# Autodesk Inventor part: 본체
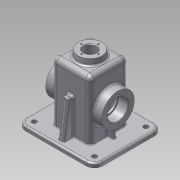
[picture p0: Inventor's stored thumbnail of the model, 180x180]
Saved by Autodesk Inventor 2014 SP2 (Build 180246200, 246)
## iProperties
Created: 2016-08
Part Number: 본체
Material: 알루미늄 6061
Document SubType Name: Modeling
Designer: user
Density: 2.71 g/cm^3
Appearance: 알루미늄 - 평지
Mass: 800.229 g
Surface Area: 911.927 cm^2
Volume: 295.287 cm^3
Author: user
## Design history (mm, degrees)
sketch "스케치1"
  geometry: L1 (-51, -57.5)-(51, -57.5); L2 (65, -43.5)-(65, 43.5); L3 (51, 57.5)-(-51, 57.5); L4 (-65, 43.5)-(-65, -43.5); L5 (-65, -57.5)-(65, 57.5); L6 (65, -57.5)-(-65, 57.5); A1 r 14 centre (-51, 43.5) between (-51, 57.5) and (-65, 43.5); A2 r 14 centre (-51, -43.5) between (-65, -43.5) and (-51, -57.5); A3 r 14 centre (51, -43.5) between (51, -57.5) and (65, -43.5); A4 r 14 centre (51, 43.5) between (65, 43.5) and (51, 57.5); 1 further point
  constraints: 12 end point, 8 point on circle, 8 point on line, 8 tangent, 4 centre point, 3 equal radius, 2 midpoint, 2 parallel, 1 horizontal, 1 perpendicular
  dimensions: "d0" = 130 distance of L6.end L5.end; "d1" = 115 distance of L5.end L6.start; "d4" = 14 radius of A1
extrude "돌출1" new body sketch "스케치1" distance "d2" = 10; taper "d3" = 0 deg
sketch "스케치2"
  geometry: L1 (-51, 0)-(51, 0) reference; L2 (32.5, 0)-(-32.5, 0); L3 (-32.5, 0)-(-32.5, 110); L4 (-32.5, 110)-(32.5, 110); L5 (32.5, 110)-(32.5, 0); 3 further points
  constraints: 8 end point, 2 midpoint, 2 parallel, 1 coincident, 1 horizontal, 1 perpendicular, 1 point on line
  dimensions: "d5" = 65 distance of L3.end L4.end; "d6" = 110 distance of L4.end L2.start
extrude "돌출2" join sketch "스케치2" stored distance "d7" = 65; taper "d8" = 0 deg
sketch "스케치3"
  geometry: L1 (27.5, 27.5)-(-27.5, 27.5); L2 (-27.5, 27.5)-(-27.5, -27.5); L3 (-27.5, -27.5)-(27.5, -27.5); L4 (27.5, -27.5)-(27.5, 27.5); L5 (27.5, 27.5)-(-27.5, -27.5); L6 (-27.5, 27.5)-(27.5, -27.5); 1 further point
  constraints: 12 end point, 2 midpoint, 2 parallel, 1 horizontal, 1 perpendicular
  dimensions: "d9" = 55 distance of L3.end L2.end; "d10" = 55 distance of L2.end L1.end
extrude "돌출3" cut sketch "스케치3" distance "d11" = 105; taper "d12" = 0 deg
sketch "스케치4"
  geometry: L1 (47.5, 55)-(-47.5, 55); L2 (47.5, 55)-(47.5, 82.5); L3 (-47.5, 82.5)-(-47.5, 55); L4 (32.5, 10)-(32.5, 110) reference; L5 (-32.5, 110)-(-32.5, 10) reference; L6 (47.5, 82.5)-(32.5, 82.5); L7 (-32.5, 82.5)-(-47.5, 82.5); L8 (32.5, 82.5)-(32.5, 55); L9 (-32.5, 82.5)-(-32.5, 55); 2 further points
  constraints: 14 end point, 6 point on line, 3 perpendicular, 1 horizontal, 1 midpoint, 1 parallel, 1 vertical alignment
  dimensions: "d13" = 55 distance from line of point (0, 0) L1; "d14" = 95 distance of L1.start L1.end; "d15" = 55 diameter of L6 L1; "d16" = 55 diameter of L7 L1
revolve "회전1" sketch "스케치4" stored, may be unused: angle "d17" = 90 deg
sketch "스케치5"
  geometry: L1 (47.5, 27.5)-(47.5, 82.5) reference; L2 (-47.5, 27.5)-(-47.5, 82.5) reference; L3 (47.5, 55)-(-47.5, 55); L4 (47.5, 55)-(47.5, 72.5); L5 (30.5, 72.2)-(30.5, 70); L6 (30.5, 70)-(27.5, 70); L7 (47.5, 72.5)-(30.8, 72.5); L8 (27.5, 0)-(27.5, 105) reference; L9 (-27.5, 0)-(-27.5, 105) reference; L10 (27.5, 55)-(27.5, 70); L11 (-47.5, 55)-(-47.5, 72.5); L12 (-47.5, 72.5)-(-30.8, 72.5); L13 (-30.5, 72.2)-(-30.5, 70); L14 (-30.5, 70)-(-27.5, 70); L15 (-27.5, 70)-(-27.5, 55); A1 r 0.3 centre (30.8, 72.2) between (30.8, 72.5) and (30.5, 72.2); A2 r 0.3 centre (-30.8, 72.2) between (-30.5, 72.2) and (-30.8, 72.5); 3 further points
  constraints: 22 end point, 12 point on line, 4 perpendicular, 4 point on circle, 4 tangent, 2 centre point, 2 midpoint, 2 parallel, 1 equal radius
  dimensions: "d18" = 17 distance between parallel lines of L5 L1; "d19" = 17 distance between parallel lines of L2 L13; "d20" = 35 diameter of L7 L3; "d21" = 30 diameter of L6 L3; "d22" = 35 diameter of L12 L3; "d23" = 30 diameter of L14 L3; "d146" = 0.3 radius of A1
revolve "회전2" sketch "스케치5" stored, may be unused: angle "d24" = 90 deg
node "작업 평면1"
sketch "스케치6"
  geometry: C1 r 20 at (0, 0); 1 further point
  constraints: 1 centre point, 1 coincident
  dimensions: "d26" = 40 diameter of C1
extrude "돌출4" join sketch "스케치6" stored distance "d27" = 105; taper "d28" = 7 deg
sketch "스케치7"
  geometry: L1 (-49.5, 10)-(-41.068, 70); L2 (-43.5, 10)-(-57.5, 10) reference; L3 (-57.5, 0)-(-57.5, 10) reference; L4 (-32.5, 110)-(-32.5, 10) reference; L5 (-41.068, 70)-(-32.5, 70); 1 further point
  constraints: 4 end point, 2 point on line, 1 perpendicular
  dimensions: "d29" = 8 distance of L1.start L2.end; "d30" = 8 deg angle of L1 L3; "d31" = 70 vertical distance of point (0, 0) L1.end
feature "리브1" sketch "스케치7" dims "d32" = 1, "d33" = 10, "d34" = 0, "d35" = 0, "d36" = 1, "d37" = 1
sketch "스케치8"
  geometry: L1 (57.5, 10)-(43.5, 10) reference; L2 (57.5, 0)-(57.5, 10) reference; L3 (32.5, 10)-(32.5, 110) reference; L4 (49.5, 10)-(41.068, 70); L5 (41.068, 70)-(32.5, 70); 1 further point
  constraints: 4 end point, 2 point on line, 1 perpendicular
  dimensions: "d38" = 70 vertical distance of point (0, 0) L4.end; "d39" = 8 deg angle of L4 L2; "d40" = 8 distance from line of L2 L4.start
feature "리브2" sketch "스케치8" dims "d41" = 1, "d42" = 10, "d43" = 0, "d44" = 0, "d45" = 1, "d46" = 1
sketch "스케치9"
  geometry: L1 (51, 10)-(-51, 10) reference; L2 (-47.5, 27.5)-(-32.5, 27.5) reference; L3 (-42.5, 10)-(-42.5, 27.5); L4 (-27.5, 0)-(-27.5, 105) reference; 1 further point
  constraints: 2 end point, 2 point on line, 1 perpendicular
  dimensions: "d47" = 15 distance between parallel lines of L4 L3
feature "리브3" sketch "스케치9" dims "d48" = 1, "d49" = 6, "d50" = 0, "d51" = 0, "d52" = 1, "d53" = 1
sketch "스케치10"
  geometry: L1 (51, 10)-(-51, 10) reference; L2 (32.5, 27.5)-(47.5, 27.5) reference; L3 (42.5, 10)-(42.5, 27.5); L4 (27.5, 0)-(27.5, 105) reference; 1 further point
  constraints: 2 end point, 2 point on line, 1 perpendicular
  dimensions: "d54" = 15 distance between parallel lines of L3 L4
feature "리브4" sketch "스케치10" dims "d55" = 1, "d56" = 6, "d57" = 0, "d58" = 0, "d59" = 1, "d60" = 1
sketch "스케치11"
  geometry: L1 (-65, -43.5)-(-65, 43.5) reference; L2 (51, -57.5)-(-51, -57.5) reference; L3 (65, 43.5)-(65, -43.5) reference; L4 (-51, 57.5)-(51, 57.5) reference; L5 (27.5, 27.5)-(27.5, -27.5) reference; L6 (27.5, -27.5)-(-27.5, -27.5) reference; L7 (-27.5, -27.5)-(-27.5, 27.5) reference; L8 (-27.5, 27.5)-(27.5, 27.5) reference; L9 (60, 43.5)-(60, -43.5); L10 (51, -52.5)-(-51, -52.5); L11 (-60, -43.5)-(-60, 43.5); L12 (-51, 52.5)-(51, 52.5); A1 r 14 centre (-51, -43.5) between (-65, -43.5) and (-51, -57.5) reference; A2 r 14 centre (51, -43.5) between (51, -57.5) and (65, -43.5) reference; A3 r 14 centre (51, 43.5) between (65, 43.5) and (51, 57.5) reference; A4 r 14 centre (-51, 43.5) between (-51, 57.5) and (-65, 43.5) reference; A5 r 9 centre (51, 43.5) between (60, 43.5) and (51, 52.5); A6 r 9 centre (51, -43.5) between (51, -52.5) and (60, -43.5); A7 r 9 centre (-51, -43.5) between (-60, -43.5) and (-51, -52.5); A8 r 9 centre (-51, 43.5) between (-51, 52.5) and (-60, 43.5); 1 further point
  constraints: 8 end point, 8 point on circle, 4 centre point, 7 other
  dimensions: "d61" = 5 distance between parallel lines of L11 L1
extrude "돌출5" cut sketch "스케치11" distance "d62" = 3; taper "d63" = 0 deg
sketch "스케치12"
  geometry: C1 r 27.5 at (0, 0) reference; A1 r 21 centre (0, 0) between (-21, 0) and (21, 0); 3 further points
  constraints: 4 point on circle, 2 horizontal alignment, 2 vertical alignment, 1 centre point, 1 coincident
  dimensions: "d64" = 42 diameter of A1
hole "구멍1" sketch "스케치12" at (-21, 0), (21, 0), (0, -21), (0, 21) diameter "d65" = 3.242; stored, may be unused: countersink angle "d69" = 90 deg, drill point angle "d71" = 118 deg; dims "d66" = 8, "d67" = 4, "d68" = 2, "d70" = 10
sketch "스케치13"
  geometry: C1 r 27.5 at (0, 0) reference; A1 r 21 centre (0, 0) between (21, 0) and (-21, 0); 3 further points
  constraints: 4 point on circle, 2 horizontal alignment, 2 vertical alignment, 1 centre point, 1 coincident
  dimensions: "d72" = 42 diameter of A1
hole "구멍2" sketch "스케치13" at (21, 0), (-21, 0), (0, 21), (0, -21) diameter "d73" = 3.242; stored, may be unused: countersink angle "d77" = 90 deg, drill point angle "d79" = 118 deg; dims "d74" = 8, "d75" = 4, "d76" = 2, "d78" = 10
sketch "스케치14"
  geometry: A1 r 14.5 centre (0, 0) between (14.5, 0) and (0, 14.5); 3 further points
  constraints: 4 point on circle, 2 horizontal alignment, 2 vertical alignment, 1 centre point, 1 coincident
  dimensions: "d80" = 29 diameter of A1
hole "구멍3" sketch "스케치14" at (14.5, 0), (0, 14.5), (-14.5, 0), (0, -14.5) diameter "d81" = 2.459; stored, may be unused: countersink angle "d85" = 90 deg, drill point angle "d87" = 118 deg; dims "d82" = 7, "d83" = 4, "d84" = 2, "d86" = 9
hole "구멍4" diameter "d90" = 21; stored, may be unused: countersink angle "d94" = 90 deg, drill point angle "d96" = 118 deg; dims "d88" = 10, "d89" = 10, "d91" = 7, "d92" = 4, "d93" = 2, "d95" = 9
hole "구멍5" diameter "d99" = 8; stored, may be unused: countersink angle "d103" = 90 deg, drill point angle "d105" = 118 deg; dims "d97" = 10, "d98" = 10, "d100" = 7, "d101" = 4, "d102" = 2, "d104" = 9
hole "구멍6" diameter "d108" = 8; stored, may be unused: countersink angle "d112" = 90 deg, drill point angle "d114" = 118 deg; dims "d106" = 10, "d107" = 10, "d109" = 7, "d110" = 4, "d111" = 2, "d113" = 9
hole "구멍7" diameter "d117" = 8; stored, may be unused: countersink angle "d121" = 90 deg, drill point angle "d123" = 118 deg; dims "d115" = 10, "d116" = 10, "d118" = 7, "d119" = 4, "d120" = 2, "d122" = 9
hole "구멍8" diameter "d126" = 8; stored, may be unused: countersink angle "d130" = 90 deg, drill point angle "d132" = 118 deg; dims "d124" = 10, "d125" = 10, "d127" = 7, "d128" = 4, "d129" = 2, "d131" = 9
sketch "스케치15"
  geometry: L1 (-100, 65)-(0, 65) reference; L2 (10, 12.5)-(10, 52.5) reference; 2 further points
  constraints: 1 other
  dimensions: "d133" = 32.5 distance from line of L1 point (-16, 32.5); "d134" = 26 distance from line of point (-16, 32.5) L2
feature "엠보싱1" sketch "스케치15" dims "d5" = 65, "d6" = 110, "d135" = 0.5, "d136" = 0
fillet "모깎기1" dims "d137" = 8
fillet "모깎기2" dims "d138" = 8
fillet "모깎기3" dims "d139" = 3
fillet "모깎기4" dims "d140" = 3
fillet "모깎기5" dims "d141" = 3
fillet "모깎기6" dims "d142" = 3
fillet "모깎기7" dims "d143" = 3
fillet "모깎기8" dims "d144" = 3
fillet "모깎기9" dims "d145" = 3
chamfer "모따기1" distance "d147" = 1; stored, may be unused: second distance "d148" = 2, angle "d149" = 45 deg
fillet "모깎기10" dims "d150" = 1
node "솔리드1"
node "투영된 루프1"
